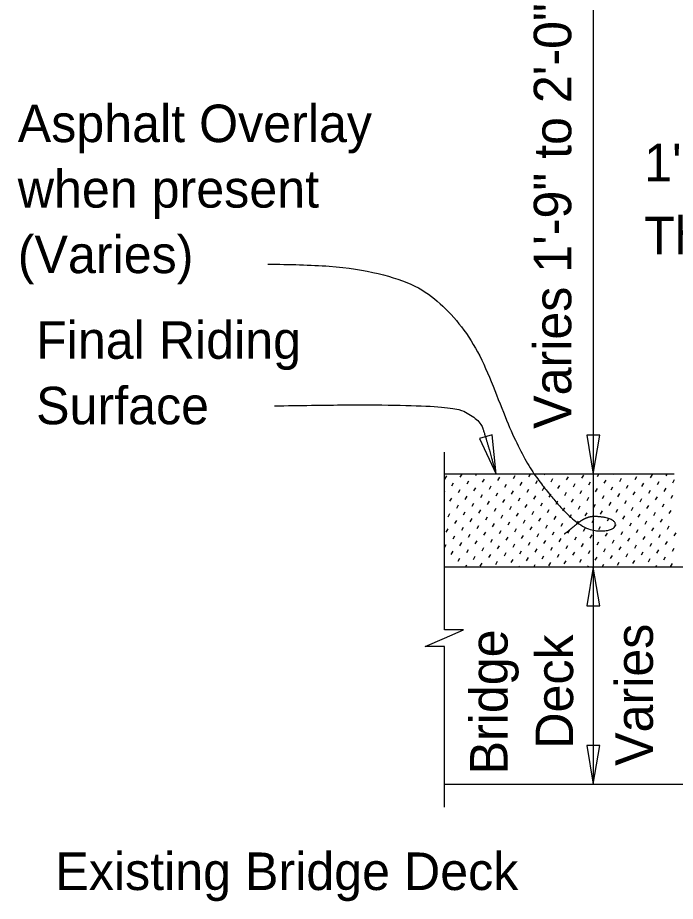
# Model space of a CAD drawing. Extents: x 21516.9 to 21586.2, y 56156.7 to 56193.6.
# Drawn here: x 21519.287 to 21522.82, y 56180.968 to 56185.716 of the extents above; entities that cross this region are included whole.
import ezdxf

# ---------------------------------------------------------------- set-up
doc = ezdxf.new("R2010")
doc.units = 0
for name, color, linetype in [('AdhocPoint_dp', 7, 'Continuous'), ('Patterning', 7, 'Continuous'), ('PlotBorder_dp', 7, 'Continuous'), ('SheetBorder_dp', 7, 'Continuous')]:
    doc.layers.add(name, color=color, linetype=linetype)

msp = doc.modelspace()

# ---------------------------------------------------------------- linework, layer by layer
at = {"layer": 'AdhocPoint_dp'}
for p, q in [((21525.5123, 56182.7637), (21521.5789, 56182.7637)), ((21521.5789, 56181.597), (21528.2206, 56181.597))]:
    msp.add_line(p, q, dxfattribs=at)
at = {"layer": 'Patterning'}
for p, q in [((21522.814, 56183.2637), (21521.5789, 56183.2637)), ((21521.5817, 56183.2372), (21521.5914, 56183.254)), ((21521.6647, 56183.247), (21521.6743, 56183.2637)), ((21521.7476, 56183.2567), (21521.7517, 56183.2637)), ((21521.8671, 56183.2298), (21521.8769, 56183.2466)), ((21521.9501, 56183.2395), (21521.9598, 56183.2563)), ((21522.033, 56183.2492), (21522.0414, 56183.2637)), ((21522.1159, 56183.259), (21522.1187, 56183.2637)), ((21522.2355, 56183.2321), (21522.2452, 56183.2489)), ((21522.3184, 56183.2418), (21522.3282, 56183.2586)), ((21522.4014, 56183.2515), (21522.4084, 56183.2637)), ((21522.4843, 56183.2613), (21522.4857, 56183.2637)), ((21522.5209, 56183.2246), (21522.5306, 56183.2414)), ((21522.6039, 56183.2344), (21522.6136, 56183.2512)), ((21522.6868, 56183.2441), (21522.6965, 56183.2609)), ((21522.7697, 56183.2538), (21522.7755, 56183.2637)), ((21521.6183, 56183.2006), (21521.628, 56183.2174)), ((21521.7013, 56183.2104), (21521.711, 56183.2272)), ((21521.7842, 56183.2201), (21521.7939, 56183.2369)), ((21521.8208, 56183.1835), (21521.8305, 56183.2003)), ((21521.9037, 56183.1932), (21521.9135, 56183.21)), ((21521.9867, 56183.2029), (21521.9964, 56183.2197)), ((21522.0696, 56183.2126), (21522.0793, 56183.2294)), ((21522.1526, 56183.2224), (21522.1623, 56183.2392)), ((21522.1892, 56183.1858), (21522.1989, 56183.2025)), ((21522.2721, 56183.1955), (21522.2818, 56183.2123)), ((21522.355, 56183.2052), (21522.3648, 56183.222)), ((21522.438, 56183.2149), (21522.4477, 56183.2317)), ((21522.4746, 56183.1783), (21522.4843, 56183.1951)), ((21522.5575, 56183.188), (21522.5672, 56183.2048)), ((21522.6405, 56183.1978), (21522.6502, 56183.2146)), ((21522.7234, 56183.2075), (21522.7331, 56183.2243)), ((21522.8063, 56183.2172), (21522.8161, 56183.234)), ((21521.5789, 56183.1663), (21521.5817, 56183.1711)), ((21521.6549, 56183.164), (21521.6647, 56183.1808)), ((21521.7379, 56183.1737), (21521.7476, 56183.1905)), ((21521.7745, 56183.1371), (21521.7842, 56183.1539)), ((21521.8574, 56183.1469), (21521.8671, 56183.1637)), ((21521.9403, 56183.1566), (21521.9501, 56183.1734)), ((21522.0233, 56183.1663), (21522.033, 56183.1831)), ((21522.0599, 56183.1297), (21522.0696, 56183.1465)), ((21522.1062, 56183.176), (21522.1159, 56183.1928)), ((21522.1428, 56183.1394), (21522.1526, 56183.1562)), ((21522.2258, 56183.1491), (21522.2355, 56183.1659)), ((21522.3087, 56183.1589), (21522.3184, 56183.1757)), ((21522.3916, 56183.1686), (21522.4014, 56183.1854)), ((21522.4283, 56183.132), (21522.438, 56183.1488)), ((21522.5112, 56183.1417), (21522.5209, 56183.1585)), ((21522.5941, 56183.1514), (21522.6039, 56183.1682)), ((21522.6771, 56183.1612), (21522.6868, 56183.1779)), ((21522.76, 56183.1709), (21522.7697, 56183.1877)), ((21522.7966, 56183.1343), (21522.8063, 56183.1511)), ((21521.6086, 56183.1177), (21521.6183, 56183.1345)), ((21521.6915, 56183.1274), (21521.7013, 56183.1442)), ((21521.7281, 56183.0908), (21521.7379, 56183.1076)), ((21521.8111, 56183.1005), (21521.8208, 56183.1173)), ((21521.894, 56183.1103), (21521.9037, 56183.1271)), ((21521.977, 56183.12), (21521.9867, 56183.1368)), ((21522.0136, 56183.0834), (21522.0233, 56183.1002)), ((21522.0965, 56183.0931), (21522.1062, 56183.1099)), ((21522.1794, 56183.1028), (21522.1892, 56183.1196)), ((21522.2624, 56183.1125), (21522.2721, 56183.1293)), ((21522.3453, 56183.1223), (21522.355, 56183.1391)), ((21522.3819, 56183.0857), (21522.3916, 56183.1024)), ((21522.4649, 56183.0954), (21522.4746, 56183.1122)), ((21522.5478, 56183.1051), (21522.5575, 56183.1219)), ((21522.6307, 56183.1148), (21522.6405, 56183.1316)), ((21522.7137, 56183.1245), (21522.7234, 56183.1413)), ((21522.7503, 56183.0879), (21522.76, 56183.1047)), ((21521.5989, 56183.0348), (21521.6086, 56183.0516)), ((21521.6452, 56183.0811), (21521.6549, 56183.0979)), ((21521.6818, 56183.0445), (21521.6915, 56183.0613)), ((21521.7648, 56183.0542), (21521.7745, 56183.071)), ((21521.8477, 56183.0639), (21521.8574, 56183.0807)), ((21521.9306, 56183.0736), (21521.9403, 56183.0904)), ((21521.9672, 56183.037), (21521.977, 56183.0538)), ((21522.0502, 56183.0468), (21522.0599, 56183.0636)), ((21522.1331, 56183.0565), (21522.1428, 56183.0733)), ((21522.216, 56183.0662), (21522.2258, 56183.083)), ((21522.299, 56183.0759), (21522.3087, 56183.0927)), ((21522.3356, 56183.0393), (21522.3453, 56183.0561)), ((21522.4185, 56183.049), (21522.4283, 56183.0658)), ((21522.5015, 56183.0588), (21522.5112, 56183.0756)), ((21522.5844, 56183.0685), (21522.5941, 56183.0853)), ((21522.6673, 56183.0782), (21522.6771, 56183.095)), ((21522.704, 56183.0416), (21522.7137, 56183.0584)), ((21522.7869, 56183.0513), (21522.7966, 56183.0681)), ((21521.6355, 56182.9982), (21521.6452, 56183.0149)), ((21521.7184, 56183.0079), (21521.7281, 56183.0247)), ((21521.8014, 56183.0176), (21521.8111, 56183.0344)), ((21521.8843, 56183.0273), (21521.894, 56183.0441)), ((21521.9209, 56182.9907), (21521.9306, 56183.0075)), ((21522.0038, 56183.0004), (21522.0136, 56183.0172)), ((21522.0868, 56183.0102), (21522.0965, 56183.027)), ((21522.1697, 56183.0199), (21522.1794, 56183.0367)), ((21522.2527, 56183.0296), (21522.2624, 56183.0464)), ((21522.2893, 56182.993), (21522.299, 56183.0098)), ((21522.3722, 56183.0027), (21522.3819, 56183.0195)), ((21522.4551, 56183.0124), (21522.4649, 56183.0292)), ((21522.5381, 56183.0222), (21522.5478, 56183.039)), ((21522.621, 56183.0319), (21522.6307, 56183.0487)), ((21522.6576, 56182.9953), (21522.6673, 56183.0121)), ((21522.7406, 56183.005), (21522.7503, 56183.0218)), ((21521.5892, 56182.9518), (21521.5989, 56182.9686)), ((21521.6721, 56182.9615), (21521.6818, 56182.9783)), ((21521.755, 56182.9713), (21521.7648, 56182.9881)), ((21521.838, 56182.981), (21521.8477, 56182.9978)), ((21521.8746, 56182.9444), (21521.8843, 56182.9612)), ((21521.9575, 56182.9541), (21521.9672, 56182.9709)), ((21522.0404, 56182.9638), (21522.0502, 56182.9806)), ((21522.1234, 56182.9735), (21522.1331, 56182.9903)), ((21522.2063, 56182.9833), (21522.216, 56183.0001)), ((21522.2429, 56182.9467), (21522.2527, 56182.9635)), ((21522.3259, 56182.9564), (21522.3356, 56182.9732)), ((21522.4088, 56182.9661), (21522.4185, 56182.9829)), ((21522.4917, 56182.9758), (21522.5015, 56182.9926)), ((21522.5284, 56182.9392), (21522.5381, 56182.956)), ((21522.5747, 56182.9856), (21522.5844, 56183.0023)), ((21522.6113, 56182.9489), (21522.621, 56182.9657)), ((21522.6942, 56182.9587), (21522.704, 56182.9755)), ((21522.7772, 56182.9684), (21522.7869, 56182.9852)), ((21521.6258, 56182.9152), (21521.6355, 56182.932)), ((21521.7087, 56182.9249), (21521.7184, 56182.9417)), ((21521.7916, 56182.9347), (21521.8014, 56182.9515)), ((21521.8282, 56182.8981), (21521.838, 56182.9148)), ((21521.9112, 56182.9078), (21521.9209, 56182.9246)), ((21521.9941, 56182.9175), (21522.0038, 56182.9343)), ((21522.0771, 56182.9272), (21522.0868, 56182.944)), ((21522.16, 56182.9369), (21522.1697, 56182.9537)), ((21522.1966, 56182.9003), (21522.2063, 56182.9171)), ((21522.2795, 56182.9101), (21522.2893, 56182.9269)), ((21522.3625, 56182.9198), (21522.3722, 56182.9366)), ((21522.4454, 56182.9295), (21522.4551, 56182.9463)), ((21522.482, 56182.8929), (21522.4917, 56182.9097)), ((21522.565, 56182.9026), (21522.5747, 56182.9194)), ((21522.6479, 56182.9123), (21522.6576, 56182.9291)), ((21522.7308, 56182.9221), (21522.7406, 56182.9389)), ((21522.8138, 56182.9318), (21522.8235, 56182.9486)), ((21521.5794, 56182.8689), (21521.5892, 56182.8857)), ((21521.6624, 56182.8786), (21521.6721, 56182.8954)), ((21521.7453, 56182.8883), (21521.755, 56182.9051)), ((21521.7819, 56182.8517), (21521.7916, 56182.8685)), ((21521.8649, 56182.8614), (21521.8746, 56182.8782)), ((21521.9478, 56182.8712), (21521.9575, 56182.888)), ((21522.0307, 56182.8809), (21522.0404, 56182.8977)), ((21522.0673, 56182.8443), (21522.0771, 56182.8611)), ((21522.1137, 56182.8906), (21522.1234, 56182.9074)), ((21522.1503, 56182.854), (21522.16, 56182.8708)), ((21522.2332, 56182.8637), (21522.2429, 56182.8805)), ((21522.3161, 56182.8734), (21522.3259, 56182.8902)), ((21522.3991, 56182.8832), (21522.4088, 56182.9)), ((21522.4357, 56182.8466), (21522.4454, 56182.8634)), ((21522.5186, 56182.8563), (21522.5284, 56182.8731)), ((21522.6016, 56182.866), (21522.6113, 56182.8828)), ((21522.6845, 56182.8757), (21522.6942, 56182.8925)), ((21522.7674, 56182.8855), (21522.7772, 56182.9022)), ((21522.8041, 56182.8488), (21522.8138, 56182.8656)), ((21521.616, 56182.8323), (21521.6258, 56182.8491)), ((21521.699, 56182.842), (21521.7087, 56182.8588)), ((21521.7356, 56182.8054), (21521.7453, 56182.8222)), ((21521.8185, 56182.8151), (21521.8282, 56182.8319)), ((21521.9015, 56182.8248), (21521.9112, 56182.8416)), ((21521.9844, 56182.8346), (21521.9941, 56182.8514)), ((21522.021, 56182.798), (21522.0307, 56182.8147)), ((21522.1039, 56182.8077), (21522.1137, 56182.8245)), ((21522.1869, 56182.8174), (21522.1966, 56182.8342)), ((21522.2698, 56182.8271), (21522.2795, 56182.8439)), ((21522.3528, 56182.8368), (21522.3625, 56182.8536)), ((21522.3894, 56182.8002), (21522.3991, 56182.817)), ((21522.4723, 56182.81), (21522.482, 56182.8268)), ((21522.5552, 56182.8197), (21522.565, 56182.8365)), ((21522.6382, 56182.8294), (21522.6479, 56182.8462)), ((21522.7211, 56182.8391), (21522.7308, 56182.8559)), ((21522.7577, 56182.8025), (21522.7674, 56182.8193)), ((21521.5789, 56182.8019), (21521.5794, 56182.8027)), ((21521.6146, 56182.7637), (21521.616, 56182.7661)), ((21521.6526, 56182.7957), (21521.6624, 56182.8125)), ((21521.6919, 56182.7637), (21521.699, 56182.7759)), ((21521.7722, 56182.7688), (21521.7819, 56182.7856)), ((21521.8551, 56182.7785), (21521.8649, 56182.7953)), ((21521.9381, 56182.7882), (21521.9478, 56182.805)), ((21521.9817, 56182.7637), (21521.9844, 56182.7684)), ((21522.059, 56182.7637), (21522.0673, 56182.7781)), ((21522.1405, 56182.7711), (21522.1503, 56182.7879)), ((21522.2235, 56182.7808), (21522.2332, 56182.7976)), ((21522.3064, 56182.7905), (21522.3161, 56182.8073)), ((21522.3487, 56182.7637), (21522.3528, 56182.7707)), ((21522.426, 56182.7637), (21522.4357, 56182.7804)), ((21522.5089, 56182.7734), (21522.5186, 56182.7901)), ((21522.5918, 56182.7831), (21522.6016, 56182.7999)), ((21522.6748, 56182.7928), (21522.6845, 56182.8096)), ((21522.7157, 56182.7637), (21522.7211, 56182.773)), ((21522.7943, 56182.7659), (21522.8041, 56182.7827))]:
    msp.add_line(p, q, dxfattribs=at)
at = {"layer": 'PlotBorder_dp'}
msp.add_line((21522.3792, 56188.5971), (21522.3792, 56181.597), dxfattribs=at)
for points in [[(21521.8566, 56183.2637), (21521.8353, 56183.4739), (21521.7673, 56183.4551)], [(21522.3792, 56183.2637), (21522.4145, 56183.472), (21522.344, 56183.472)], [(21522.3792, 56182.7637), (21522.344, 56182.5555), (21522.4145, 56182.5555)], [(21522.3792, 56181.597), (21522.4145, 56181.8053), (21522.344, 56181.8053)]]:
    msp.add_lwpolyline(points, close=True, dxfattribs=at)
msp.add_lwpolyline([(21521.579, 56181.4731), (21521.579, 56182.3364), (21521.4757, 56182.3364), (21521.579, 56182.3814), (21521.6824, 56182.4264), (21521.579, 56182.4264), (21521.579, 56183.3815)], dxfattribs=at)
for points in [[(21520.6312, 56184.3923), (21521.2601, 56184.3958), (21521.7169, 56184.0712), (21521.9733, 56183.3804), (21522.1817, 56183.1023), (21522.3234, 56182.9718), (21522.4283, 56182.9534), (21522.4978, 56182.9718), (21522.4978, 56183.013), (21522.4269, 56183.0356), (21522.3405, 56183.0356), (21522.2498, 56182.9619), (21522.2228, 56182.9406)], [(21520.6663, 56183.6305), (21521.5703, 56183.6475), (21521.7671, 56183.5651), (21521.8056, 56183.4489), (21521.8566, 56183.2637)]]:
    msp.add_open_spline(points, degree=2, dxfattribs=at)

# ---------------------------------------------------------------- texts
for s, p in [('Asphalt Overlay ', (21519.2872, 56185.0475)), ('1\'-2" x 10" x ', (21522.6521, 56184.8373)), ('when present ', (21519.2872, 56184.6955)), ('Thick Neoprene Pad', (21522.6521, 56184.4449)), ('(Varies)', (21519.2872, 56184.3435)), ('Final Riding ', (21519.3856, 56183.8832)), ('Surface', (21519.3856, 56183.5312))]:
    msp.add_text(s, height=0.2016, dxfattribs=at).set_placement(p)
for s, p in [('Bridge', (21521.9187, 56181.6496)), ('Deck', (21522.2707, 56181.788))]:
    msp.add_text(s, height=0.2016, rotation=90, dxfattribs=at).set_placement(p)
at = {"layer": 'SheetBorder_dp'}
for s, p in [('Varies 1\'-9" to 2\'-0"', (21522.2608, 56183.5067)), ('Varies', (21522.6994, 56181.6956))]:
    msp.add_text(s, height=0.2016, rotation=90, dxfattribs=at).set_placement(p)
msp.add_text('Existing Bridge Deck', height=0.2016, dxfattribs=at).set_placement((21519.4891, 56181.0286))

doc.saveas('drawing.dxf')
